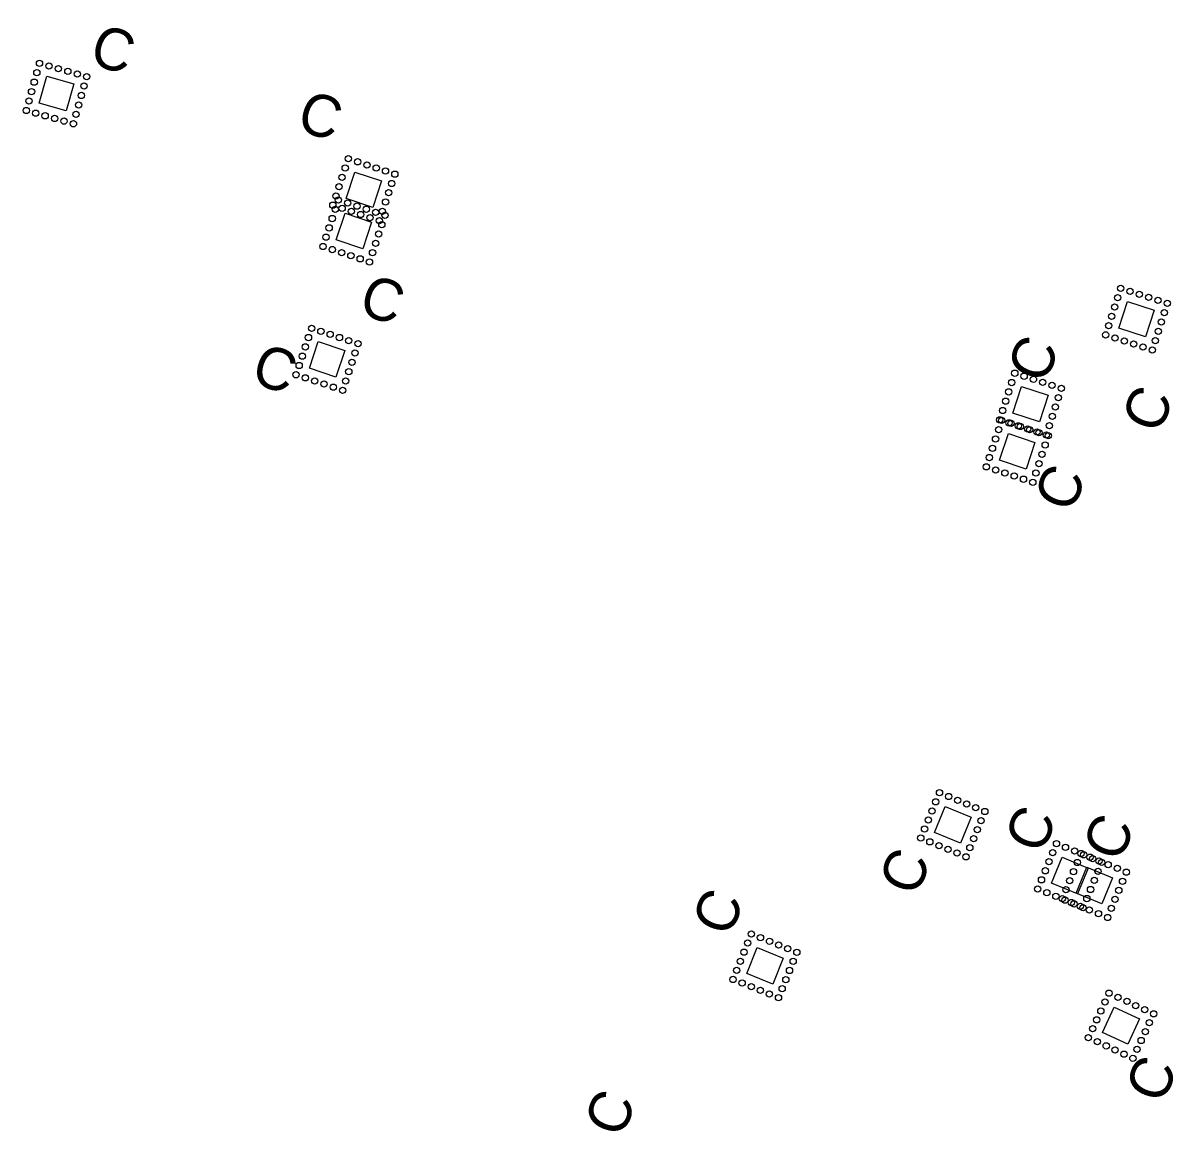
# Model space of a CAD drawing. Extents: x 2470000 to 2520000, y 340000 to 380000.
# Drawn here: x 2482960.8 to 2483373.1, y 368832.1 to 369229.7 of the extents above; entities that cross this region are included whole.
import ezdxf

# ---------------------------------------------------------------- set-up
doc = ezdxf.new("R2010")
doc.units = 0
for name, color, linetype in [('Label C CG CELL', 7, 'Continuous'), ('Prop Guardrail', 7, 'Continuous'), ('Prop Guardrail Anchor Unit CELL', 7, 'Continuous'), ('Prop Structure Anchor Unit CELL', 7, 'Continuous'), ('Rock Inlet Sediment Trap Type B CG CELL', 7, 'Continuous'), ('Rock Pipe Inlet Sediment Trap Type B Final CELL', 7, 'Continuous'), ('Scratch_Level_5', 7, 'Continuous')]:
    doc.layers.add(name, color=color, linetype=linetype)

# ---------------------------------------------------------------- blocks, each defined once
blk = doc.blocks.new('C3')
at = {"layer": 'Prop Guardrail'}
blk.add_text('C', height=0.3, dxfattribs=at).set_placement((-0.161, -0.136))
blk = doc.blocks.new('C2')
at = {"layer": 'Prop Guardrail Anchor Unit CELL'}
blk.add_text('C', height=0.3, dxfattribs=at).set_placement((-0.161, -0.136))
blk = doc.blocks.new('C1')
at = {"layer": 'Label C CG CELL'}
blk.add_text('C', height=0.3, dxfattribs=at).set_placement((-0.161, -0.136))

msp = doc.modelspace()

# ---------------------------------------------------------------- linework, layer by layer
at = {"layer": 'Prop Structure Anchor Unit CELL'}
for points in [[(2483066.21, 369115.98), (2483075.69, 369112.83), (2483072.54, 369103.34), (2483063.05, 369106.51)], [(2483346.17, 368869.35), (2483350.39, 368878.42), (2483359.46, 368874.2), (2483355.23, 368865.14)]]:
    msp.add_lwpolyline(points, close=True, dxfattribs=at)
for centre in [(2483063.83, 369120.75), (2483062.72, 369117.43), (2483067.15, 369119.64), (2483070.47, 369118.54), (2483073.79, 369117.43), (2483077.11, 369116.33), (2483061.62, 369114.1), (2483080.43, 369115.22), (2483060.52, 369110.78), (2483078.23, 369108.58), (2483079.33, 369111.9), (2483058.31, 369104.14), (2483059.41, 369107.46), (2483077.12, 369105.26), (2483061.63, 369103.04), (2483064.95, 369101.93), (2483068.27, 369100.83), (2483071.59, 369099.72), (2483076.02, 369101.94), (2483074.91, 369098.62), (2483348.55, 368883.4), (2483351.72, 368881.92), (2483345.6, 368877.05), (2483347.07, 368880.23), (2483354.9, 368880.45), (2483358.07, 368878.97), (2483361.25, 368877.5), (2483344.12, 368873.88), (2483362.94, 368872.85), (2483364.42, 368876.02), (2483342.65, 368870.7), (2483361.47, 368869.67), (2483341.17, 368867.53), (2483344.35, 368866.06), (2483359.99, 368866.5), (2483347.52, 368864.58), (2483350.69, 368863.1), (2483353.87, 368861.63), (2483358.52, 368863.33), (2483357.04, 368860.15)]:
    msp.add_circle(centre, 1.12, dxfattribs=at)
at = {"layer": 'Rock Inlet Sediment Trap Type B CG CELL'}
for points in [[(2483075.79, 369161.8), (2483085.28, 369158.64), (2483082.12, 369149.15), (2483072.64, 369152.32)], [(2483312.6, 369083.13), (2483322.09, 369079.98), (2483318.93, 369070.49), (2483309.45, 369073.65)]]:
    msp.add_lwpolyline(points, close=True, dxfattribs=at)
for centre in [(2483073.41, 369166.55), (2483072.31, 369163.23), (2483076.73, 369165.45), (2483080.05, 369164.34), (2483083.38, 369163.24), (2483086.7, 369162.13), (2483071.2, 369159.91), (2483088.91, 369157.71), (2483090.02, 369161.03), (2483069, 369153.26), (2483070.1, 369156.58), (2483087.81, 369154.39), (2483067.89, 369149.94), (2483086.71, 369151.07), (2483071.21, 369148.84), (2483074.54, 369147.73), (2483077.86, 369146.63), (2483081.18, 369145.53), (2483085.6, 369147.74), (2483084.5, 369144.42), (2483310.22, 369087.89), (2483309.12, 369084.56), (2483313.54, 369086.78), (2483316.86, 369085.68), (2483320.18, 369084.57), (2483323.51, 369083.47), (2483308.01, 369081.24), (2483325.72, 369079.05), (2483326.83, 369082.37), (2483306.91, 369077.92), (2483324.62, 369075.72), (2483304.7, 369071.28), (2483305.81, 369074.6), (2483323.52, 369072.4), (2483308.02, 369070.17), (2483311.34, 369069.07), (2483314.67, 369067.97), (2483317.99, 369066.86), (2483322.41, 369069.08), (2483321.31, 369065.76)]:
    msp.add_circle(centre, 1.12, dxfattribs=at)
at = {"layer": 'Scratch_Level_5'}
for points in [[(2482969.3, 369210.68), (2482978.93, 369207.98), (2482976.22, 369198.35), (2482966.6, 369201.07)], [(2483079.32, 369176.51), (2483088.81, 369173.36), (2483085.65, 369163.87), (2483076.17, 369167.03)], [(2483352.04, 369120.8), (2483355.11, 369130.31), (2483364.63, 369127.24), (2483361.54, 369117.73)], [(2483314.24, 369090.47), (2483317.31, 369099.98), (2483326.83, 369096.91), (2483323.75, 369087.4)], [(2483286.24, 368940.79), (2483290.06, 368950.03), (2483299.3, 368946.22), (2483295.47, 368936.98)], [(2483327.99, 368922.65), (2483331.81, 368931.89), (2483341.05, 368928.07), (2483337.23, 368918.84)], [(2483336.74, 368919.12), (2483340.56, 368928.37), (2483349.8, 368924.55), (2483345.98, 368915.31)], [(2483219.2, 368890.37), (2483222.93, 368899.65), (2483232.21, 368895.91), (2483228.46, 368886.64)]]:
    msp.add_lwpolyline(points, close=True, dxfattribs=at)
for centre in [(2482966.71, 369215.33), (2482965.76, 369211.96), (2482970.08, 369214.38), (2482973.45, 369213.43), (2482976.82, 369212.49), (2482980.18, 369211.54), (2482964.81, 369208.59), (2482982.61, 369207.22), (2482983.55, 369210.59), (2482963.86, 369205.22), (2482981.66, 369203.85), (2482962.92, 369201.85), (2482980.71, 369200.48), (2482961.97, 369198.48), (2482965.34, 369197.53), (2482968.71, 369196.59), (2482972.08, 369195.64), (2482975.45, 369194.69), (2482979.76, 369197.11), (2482978.82, 369193.74), (2483075.84, 369177.95), (2483076.94, 369181.27), (2483080.26, 369180.17), (2483083.59, 369179.06), (2483086.91, 369177.96), (2483074.73, 369174.63), (2483090.23, 369176.85), (2483093.55, 369175.75), (2483073.63, 369171.31), (2483092.45, 369172.43), (2483072.53, 369167.99), (2483090.24, 369165.79), (2483091.34, 369169.11), (2483071.42, 369164.67), (2483074.74, 369163.56), (2483078.06, 369162.46), (2483089.13, 369162.46), (2483081.38, 369161.35), (2483084.71, 369160.25), (2483088.03, 369159.14), (2483352.68, 369135.03), (2483356.01, 369133.96), (2483359.34, 369132.88), (2483351.6, 369131.7), (2483362.67, 369131.81), (2483366, 369130.73), (2483369.33, 369129.66), (2483349.45, 369125.04), (2483350.53, 369128.37), (2483368.25, 369126.32), (2483348.37, 369121.71), (2483367.18, 369122.99), (2483347.3, 369118.38), (2483350.63, 369117.3), (2483353.96, 369116.23), (2483365.03, 369116.33), (2483366.1, 369119.66), (2483357.29, 369115.15), (2483360.62, 369114.08), (2483363.95, 369113), (2483314.88, 369104.7), (2483313.8, 369101.37), (2483318.21, 369103.63), (2483321.54, 369102.55), (2483324.87, 369101.48), (2483328.2, 369100.4), (2483312.73, 369098.04), (2483330.46, 369096), (2483331.53, 369099.33), (2483310.58, 369091.38), (2483311.65, 369094.71), (2483329.38, 369092.66), (2483309.5, 369088.05), (2483328.31, 369089.33), (2483312.83, 369086.97), (2483316.16, 369085.9), (2483319.49, 369084.82), (2483322.83, 369083.75), (2483327.23, 369086), (2483326.16, 369082.67), (2483286.67, 368951.7), (2483288, 368954.93), (2483291.24, 368953.59), (2483294.47, 368952.26), (2483285.33, 368948.46), (2483297.71, 368950.92), (2483300.94, 368949.59), (2483304.18, 368948.25), (2483283.99, 368945.23), (2483302.84, 368945.01), (2483282.66, 368941.99), (2483301.5, 368941.78), (2483281.32, 368938.76), (2483284.56, 368937.42), (2483287.79, 368936.08), (2483291.03, 368934.75), (2483298.83, 368935.31), (2483300.17, 368938.54), (2483329.76, 368936.79), (2483332.99, 368935.45), (2483294.26, 368933.41), (2483297.5, 368932.07), (2483328.42, 368933.55), (2483336.23, 368934.12), (2483338.51, 368933.26), (2483339.46, 368932.78), (2483341.74, 368931.93), (2483342.7, 368931.44), (2483344.98, 368930.59), (2483325.75, 368927.08), (2483327.09, 368930.32), (2483335.84, 368926.79), (2483337.17, 368930.03), (2483344.6, 368926.87), (2483345.93, 368930.11), (2483348.21, 368929.25), (2483351.45, 368927.92), (2483354.68, 368926.58), (2483324.41, 368923.85), (2483334.5, 368923.56), (2483343.26, 368923.64), (2483353.35, 368923.35), (2483323.08, 368920.61), (2483326.31, 368919.28), (2483333.16, 368920.32), (2483341.92, 368920.4), (2483352.01, 368920.11), (2483329.55, 368917.94), (2483331.83, 368917.09), (2483332.78, 368916.6), (2483335.06, 368915.75), (2483336.02, 368915.27), (2483338.3, 368914.42), (2483340.59, 368917.17), (2483350.67, 368916.88), (2483339.25, 368913.93), (2483341.53, 368913.08), (2483344.77, 368911.74), (2483348, 368910.41), (2483349.34, 368913.64), (2483220.83, 368904.53), (2483224.08, 368903.22), (2483227.33, 368901.91), (2483218.22, 368898.03), (2483219.53, 368901.28), (2483230.57, 368900.6), (2483233.82, 368899.3), (2483237.07, 368897.99), (2483216.91, 368894.79), (2483235.76, 368894.74), (2483215.6, 368891.54), (2483234.45, 368891.5), (2483214.3, 368888.29), (2483217.54, 368886.99), (2483220.79, 368885.68), (2483233.15, 368888.25), (2483224.04, 368884.37), (2483227.28, 368883.06), (2483230.53, 368881.76), (2483231.84, 368885)]:
    msp.add_circle(centre, 1.12, dxfattribs=at)

# ---------------------------------------------------------------- block references
at = {"layer": 'Label C CG CELL'}
for name, p, xscale, yscale, rotation in [('C1', (2483089.78, 369130.1), 49.99999999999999, 50, -18.37550694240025), ('C3', (2483331.93, 369064.41), 50, 49.99999999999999, 67.56305879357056)]:
    msp.add_blockref(name, p, dxfattribs=dict(at, xscale=xscale, yscale=yscale, rotation=rotation))
at = {"layer": 'Prop Guardrail Anchor Unit CELL', "xscale": 50, "yscale": 50, "rotation": 68.05623472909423}
msp.add_blockref('C2', (2483364.49, 368853.39), dxfattribs=at)
at = {"layer": 'Prop Structure Anchor Unit CELL', "xscale": 50, "yscale": 50.00000000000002, "rotation": -18.38982551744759}
msp.add_blockref('C2', (2483051.39, 369105.43), dxfattribs=at)
at = {"layer": 'Rock Pipe Inlet Sediment Trap Type B Final CELL', "xscale": 50, "yscale": 50, "rotation": 67.56305879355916}
for p in [(2483321.42, 368942.58), (2483349.26, 368939.69)]:
    msp.add_blockref('C3', p, dxfattribs=at)
at = {"layer": 'Scratch_Level_5', "xscale": 50}
for p, yscale, rotation in [((2482993.6, 369219.47), 50, -18.361190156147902), ((2483067.6, 369195.78), 50, -18.361190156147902), ((2483322.35, 369110.44), 49.99999999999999, 67.56305879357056), ((2483363.18, 369092.54), 49.99999999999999, 67.56305879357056), ((2483276.51, 368927.45), 49.99999999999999, 67.56305879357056), ((2483209.81, 368913.01), 49.99999999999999, 67.56305879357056), ((2483171.27, 368841.26), 49.99999999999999, 67.56305879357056)]:
    msp.add_blockref('C3', p, dxfattribs=dict(at, yscale=yscale, rotation=rotation))

doc.saveas('drawing.dxf')
